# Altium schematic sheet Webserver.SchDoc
size A
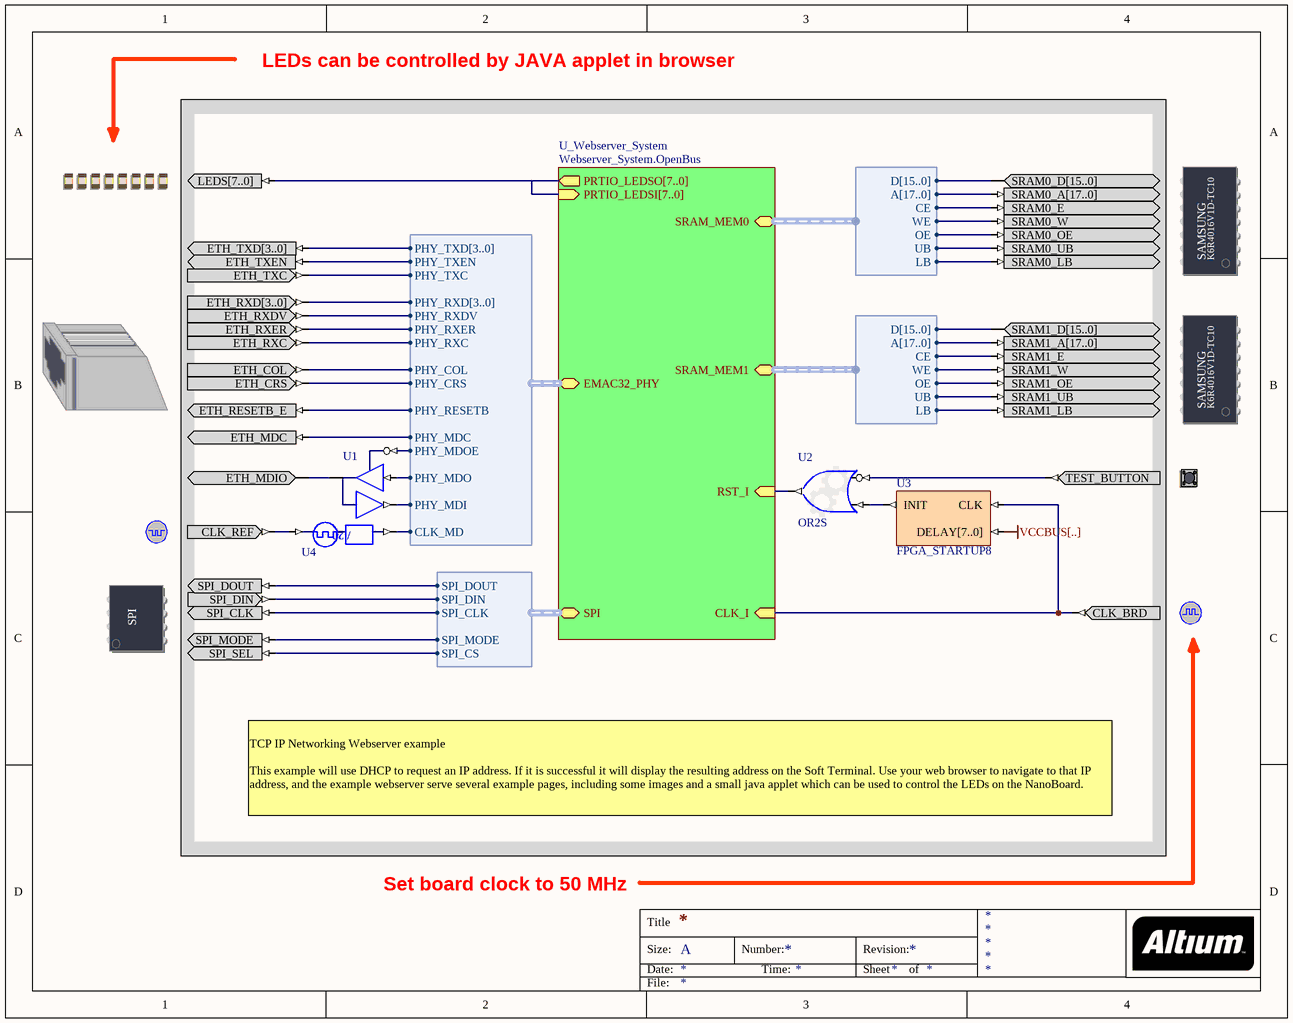
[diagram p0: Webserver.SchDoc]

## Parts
(Parts that share a designator on the sheet are numbered #1, #2 ... from top to bottom, then left to right.)
?#1  LED  (value not drawn)
?#2  SRAM_DAUGHTER0  (value not drawn)
?#3  ETH_PHY  (value not drawn)
?#4  SRAM_DAUGHTER1  (value not drawn)
?#5  TEST_BUTTON  (value not drawn)
?#6  CLOCK_REFERENCE  (value not drawn)
?#7  SERIALFMEMORY  (value not drawn)
?#8  CLOCK_BOARD  (value not drawn)
U1  IOBUF  (value not drawn)
U2  OR2S
U3  FPGA_STARTUP8
U4  CDIV20DC50  (value not drawn)

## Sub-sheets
U_Webserver_System = Webserver_System.OpenBus: RST_I (in), CLK_I (in), EMAC32_PHY (harness EMAC32), SRAM_MEM0 (harness WB_MEM_CTRL_SRAM16_A18), SRAM_MEM1 (harness WB_MEM_CTRL_SRAM16_A18), PRTIO_LEDSO[7..0] (out), PRTIO_LEDSI[7..0] (in), SPI (harness SPI_W_NB)

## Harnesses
EMAC32: PHY_TXD[3..0], PHY_TXEN, PHY_TXC, PHY_RXD[3..0], PHY_RXDV, PHY_RXER, PHY_RXC, PHY_COL, PHY_CRS, PHY_RESETB, PHY_MDC, PHY_MDOE, PHY_MDO, PHY_MDI, CLK_MD
WB_MEM_CTRL_SRAM16_A18: D[15..0], A[17..0], CE, WE, OE, UB, LB
SPI_W_NB: SPI_DOUT, SPI_DIN, SPI_CLK, SPI_MODE, SPI_CS

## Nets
VCCBUS[..]: U3.DELAY[7..0]
Net?#2_SRAM0_E: ?#2.SRAM0_E ; sheet U_Webserver_System/SRAM_MEM0.CE
Net?#2_SRAM0_LB: ?#2.SRAM0_LB ; sheet U_Webserver_System/SRAM_MEM0.LB
Net?#2_SRAM0_OE: ?#2.SRAM0_OE ; sheet U_Webserver_System/SRAM_MEM0.OE
Net?#2_SRAM0_UB: ?#2.SRAM0_UB ; sheet U_Webserver_System/SRAM_MEM0.UB
Net?#2_SRAM0_W: ?#2.SRAM0_W ; sheet U_Webserver_System/SRAM_MEM0.WE
Net?#3_ETH_COL: ?#3.ETH_COL ; sheet U_Webserver_System/EMAC32_PHY.PHY_COL
Net?#3_ETH_CRS: ?#3.ETH_CRS ; sheet U_Webserver_System/EMAC32_PHY.PHY_CRS
Net?#3_ETH_MDC: ?#3.ETH_MDC ; sheet U_Webserver_System/EMAC32_PHY.PHY_MDC
Net?#3_ETH_MDIO: ?#3.ETH_MDIO U1.IO
Net?#3_ETH_RESETB_E: ?#3.ETH_RESETB_E ; sheet U_Webserver_System/EMAC32_PHY.PHY_RESETB
Net?#3_ETH_RXC: ?#3.ETH_RXC ; sheet U_Webserver_System/EMAC32_PHY.PHY_RXC
Net?#3_ETH_RXDV: ?#3.ETH_RXDV ; sheet U_Webserver_System/EMAC32_PHY.PHY_RXDV
Net?#3_ETH_RXER: ?#3.ETH_RXER ; sheet U_Webserver_System/EMAC32_PHY.PHY_RXER
Net?#3_ETH_TXC: ?#3.ETH_TXC ; sheet U_Webserver_System/EMAC32_PHY.PHY_TXC
Net?#3_ETH_TXEN: ?#3.ETH_TXEN ; sheet U_Webserver_System/EMAC32_PHY.PHY_TXEN
Net?#4_SRAM1_E: ?#4.SRAM1_E ; sheet U_Webserver_System/SRAM_MEM1.CE
Net?#4_SRAM1_LB: ?#4.SRAM1_LB ; sheet U_Webserver_System/SRAM_MEM1.LB
Net?#4_SRAM1_OE: ?#4.SRAM1_OE ; sheet U_Webserver_System/SRAM_MEM1.OE
Net?#4_SRAM1_UB: ?#4.SRAM1_UB ; sheet U_Webserver_System/SRAM_MEM1.UB
Net?#4_SRAM1_W: ?#4.SRAM1_W ; sheet U_Webserver_System/SRAM_MEM1.WE
Net?#5_TEST_BUTTON: ?#5.TEST_BUTTON U2.I0
Net?#6_CLK_REF: ?#6.CLK_REF U4.CLKIN
Net?#7_SPI_CLK: ?#7.SPI_CLK ; sheet U_Webserver_System/SPI.SPI_CLK
Net?#7_SPI_DIN: ?#7.SPI_DIN ; sheet U_Webserver_System/SPI.SPI_DIN
Net?#7_SPI_DOUT: ?#7.SPI_DOUT ; sheet U_Webserver_System/SPI.SPI_DOUT
Net?#7_SPI_MODE: ?#7.SPI_MODE ; sheet U_Webserver_System/SPI.SPI_MODE
Net?#7_SPI_SEL: ?#7.SPI_SEL ; sheet U_Webserver_System/SPI.SPI_CS
Net?#8_CLK_BRD: ?#8.CLK_BRD U3.CLK ; sheet U_Webserver_System/CLK_I
NetU1_I: U1.I ; sheet U_Webserver_System/EMAC32_PHY.PHY_MDO
NetU1_O: U1.O ; sheet U_Webserver_System/EMAC32_PHY.PHY_MDI
NetU1_T: U1.T ; sheet U_Webserver_System/EMAC32_PHY.PHY_MDOE
NetU2_I1: U2.I1 U3.INIT
NetU2_O: U2.O ; sheet U_Webserver_System/RST_I
NetU4_CLKDV: U4.CLKDV ; sheet U_Webserver_System/EMAC32_PHY.CLK_MD

Not connected (* = marked no-connect by the designer): ?#1 LEDS[7..0]; ?#2 SRAM0_A[17..0] SRAM0_D[15..0]; ?#3 ETH_RXD[3..0] ETH_TXD[3..0]; ?#4 SRAM1_A[17..0] SRAM1_D[15..0]

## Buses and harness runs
bus sheet U_Webserver_System/PRTIO_LEDSI[7..0] = sheet U_Webserver_System/PRTIO_LEDSO[7..0]

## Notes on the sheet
- LEDs can be controlled by JAVA applet in browser
- TCP IP Networking Webserver example
  This example will use DHCP to request an IP address. If it is successful it will display the resulting address on the Soft Terminal. Use your web browser to navigate to that IP address, and the example webserver serve several example pages, including some images and a small java applet which can be used to control the LEDs on the NanoBoard.
- Set board clock to 50 MHz

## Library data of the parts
?#1 = LED: Bank of eight Red LEDs; PortComponent: True
?#2 = SRAM_DAUGHTER0: Free Static RAM - Daughterboard; PortComponent: True
?#3 = ETH_PHY: Ethernet PHY-interface; PortComponent: True
?#4 = SRAM_DAUGHTER1: Free Static RAM - Daughterboard; PortComponent: True
?#5 = TEST_BUTTON: Test / Reset Button; PortComponent: True
?#6 = CLOCK_REFERENCE: Global System Clock Reference Supply; PortComponent: True
?#7 = SPI_BUS: Serial SPI Flash RAM; PortComponent: True
?#8 = CLOCK_BOARD: Global System Clock Supply; PortComponent: True
U1 = iobuf: Input/Output Buffer; Enable: Low; Control: Common Control T; ArchiveName: GENERIC; VHDLIB_SIM: GENERIC_LIB
U2 = GATE: Configurable Generic Gate; ConfiguratorName: GENERIC_GATE; ConfigurationParameters: {}Version[1.0]{}GateKind[OR]{}BusInput[False]{}GateInputType[Bit]{}GateOutputOption[Normal]{}BusWidth[8]{}RegisterOutputs[False]{}NegativeClockEdge[False]{}InputCount[2]{}InputInvert0[True]{}InputInvert1[False]{}
U3 = FPGA_STARTUP8: FPGA Startup With 8 Bit Delay
U4 = CDIV20DC50: Clock Divider by 20 with 50% Duty Cycle Output; DivisorRate: 20; DutyCycle: 50; ArchiveName: GENERIC; VHDLIB_SIM: GENERIC_LIB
